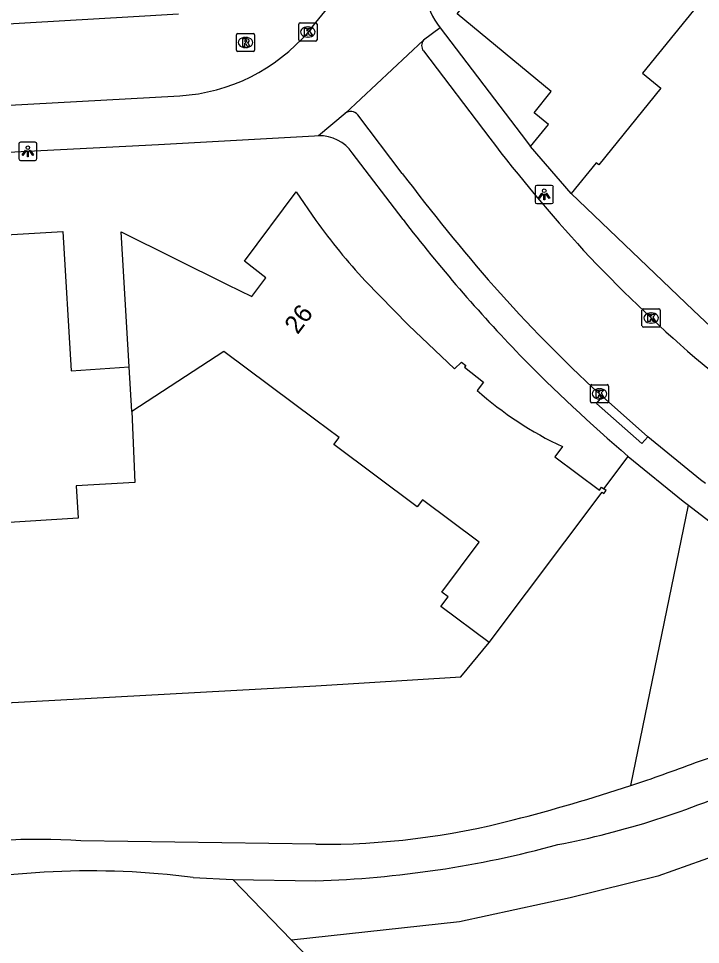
# Model space of a CAD drawing. Extents: x 159503 to 160347, y 382525 to 383272.
# Drawn here: x 159983.7 to 160021.1, y 382910.4 to 382961.2 of the extents above; entities that cross this region are included whole.
import ezdxf

# ---------------------------------------------------------------- set-up
doc = ezdxf.new("R2010")
doc.units = 0
for name, color, linetype in [('IMGEO_Fietspad_open', 7, 'Continuous'), ('IMGEO_Groenvoorziening', 7, 'Continuous'), ('IMGEO_Kolk', 7, 'Continuous'), ('IMGEO_Lichtpunt', 7, 'Continuous'), ('IMGEO_Muur', 7, 'Continuous'), ('IMGEO_Pand', 7, 'Continuous'), ('IMGEO_Pand_nummerreeks', 7, 'Continuous'), ('IMGEO_Rijbaan_lokaal_open', 7, 'Continuous'), ('IMGEO_Rioolput', 7, 'Continuous'), ('IMGEO_Voetpad_halfverhard', 7, 'Continuous'), ('IMGEO_Voetpad_open', 7, 'Continuous')]:
    doc.layers.add(name, color=color, linetype=linetype)

msp = doc.modelspace()

# ---------------------------------------------------------------- linework, layer by layer
at = {"layer": 'IMGEO_Fietspad_open'}
for points in [[(160005.905, 382959.423), (160009.545, 382954.631)], [(160004.746, 382952.7), (160002.3, 382955.907)], [(160020.788, 382942.6), (160024.456, 382939.589)], [(160015.738, 382940.446), (160015.569, 382940.601)], [(160015.738, 382940.446), (160018.22, 382938.246)], [(160021.378, 382935.67), (160021.106, 382935.882), (160018.22, 382938.246)]]:
    msp.add_lwpolyline(points, dxfattribs=at)
for centre, radius, start, end in [((160006.291, 382959.72), 0.487, 141.8673, 217.5579), ((160001.906, 382955.602), 0.498, 37.7654, 127.7017), ((160081.386, 383009.489), 90.391, 217.36539, 222.45416), ((160092.923, 383019.042), 110.347, 216.95678, 221.11214), ((160075.343, 383005.287), 83.102, 223.12889, 228.96758), ((160068.005, 382997.931), 77.694, 221.46522, 227.5527)]:
    msp.add_arc(centre, radius, start, end, dxfattribs=at)
at = {"layer": 'IMGEO_Groenvoorziening'}
for points in [[(160015.807, 382935.383), (160017.142, 382937.168)], [(160017.276, 382919.096), (160020.444, 382934.49)], [(159935.493, 382907.023), (159952.688, 382921.969), (160000, 382924.568), (160007.956, 382925.066), (160009.503, 382926.949)], [(160026.463, 382917.219), (160023.698, 382915.886), (160018.766, 382914.115), (160013.958, 382912.93), (160007.888, 382911.617), (159998.661, 382910.612)], [(159998.661, 382910.612), (159995.441, 382913.932)], [(159998.661, 382910.612), (159999.841, 382909.394), (160004.058, 382905.797), (160007.951, 382902.99), (160014.173, 382899.282), (160017.864, 382897.378), (160025.056, 382894.371), (160025.314, 382894.239)]]:
    msp.add_lwpolyline(points, dxfattribs=at)
at = {"layer": 'IMGEO_Kolk'}
for p, q in [((159999.066, 382960.039), (159999.066, 382960.891)), ((159999.141, 382960.965), (159999.993, 382960.965)), ((159999.554, 382960.745), (159999.579, 382960.745)), ((160000.067, 382960.891), (160000.067, 382960.039)), ((159999.577, 382960.185), (159999.552, 382960.185)), ((159999.993, 382959.965), (159999.141, 382959.965)), ((160017.896, 382944.34), (160017.896, 382945.192)), ((160017.971, 382945.266), (160018.823, 382945.266)), ((160018.384, 382945.046), (160018.409, 382945.046)), ((160018.897, 382945.192), (160018.897, 382944.34)), ((160018.823, 382944.266), (160017.971, 382944.266)), ((160018.407, 382944.486), (160018.382, 382944.486)), ((160015.065, 382940.177), (160015.065, 382941.029)), ((160015.14, 382941.103), (160015.992, 382941.103)), ((160015.553, 382940.883), (160015.578, 382940.883)), ((160016.066, 382941.029), (160016.066, 382940.177)), ((160015.576, 382940.323), (160015.551, 382940.323)), ((160015.992, 382940.103), (160015.14, 382940.103))]:
    msp.add_line(p, q, dxfattribs=at)
for points in [[(159999.066, 382960.039), (159999.066, 382960.891)], [(159999.141, 382960.965), (159999.993, 382960.965)], [(159999.387, 382960.665), (159999.51, 382960.665), (159999.51, 382960.514), (159999.64, 382960.665), (159999.804, 382960.665), (159999.658, 382960.514), (159999.811, 382960.265), (159999.659, 382960.265), (159999.574, 382960.429), (159999.51, 382960.362), (159999.51, 382960.265), (159999.387, 382960.265), (159999.387, 382960.665)], [(160000.067, 382960.891), (160000.067, 382960.039)], [(159999.993, 382959.965), (159999.141, 382959.965)], [(160017.896, 382944.34), (160017.896, 382945.192)], [(160017.971, 382945.266), (160018.823, 382945.266)], [(160018.217, 382944.966), (160018.34, 382944.966), (160018.34, 382944.815), (160018.47, 382944.966), (160018.634, 382944.966), (160018.488, 382944.815), (160018.641, 382944.566), (160018.489, 382944.566), (160018.404, 382944.73), (160018.34, 382944.663), (160018.34, 382944.566), (160018.217, 382944.566), (160018.217, 382944.966)], [(160018.897, 382945.192), (160018.897, 382944.34)], [(160018.823, 382944.266), (160017.971, 382944.266)], [(160015.065, 382940.177), (160015.065, 382941.029)], [(160015.14, 382941.103), (160015.992, 382941.103)], [(160015.386, 382940.803), (160015.509, 382940.803), (160015.509, 382940.652), (160015.639, 382940.803), (160015.803, 382940.803), (160015.657, 382940.652), (160015.81, 382940.403), (160015.658, 382940.403), (160015.573, 382940.567), (160015.509, 382940.5), (160015.509, 382940.403), (160015.386, 382940.403), (160015.386, 382940.803)], [(160016.066, 382941.029), (160016.066, 382940.177)], [(160015.992, 382940.103), (160015.14, 382940.103)]]:
    msp.add_lwpolyline(points, dxfattribs=at)
for centre, start, end in [((159999.143, 382960.889), 91.552, 178.448), ((159999.143, 382960.889), 91.552, 178.448), ((159999.991, 382960.889), 1.552, 88.448), ((159999.991, 382960.889), 1.552, 88.448), ((159999.143, 382960.041), 181.552, 268.448), ((159999.143, 382960.041), 181.552, 268.448), ((159999.991, 382960.041), 271.552, 358.448), ((159999.991, 382960.041), 271.552, 358.448), ((160017.973, 382945.19), 91.552, 178.448), ((160017.973, 382945.19), 91.552, 178.448), ((160018.821, 382945.19), 1.552, 88.448), ((160018.821, 382945.19), 1.552, 88.448), ((160017.973, 382944.342), 181.552, 268.448), ((160017.973, 382944.342), 181.552, 268.448), ((160018.821, 382944.342), 271.552, 358.448), ((160018.821, 382944.342), 271.552, 358.448), ((160015.142, 382941.027), 91.552, 178.448), ((160015.142, 382941.027), 91.552, 178.448), ((160015.99, 382941.027), 1.552, 88.448), ((160015.99, 382941.027), 1.552, 88.448), ((160015.142, 382940.179), 181.552, 268.448), ((160015.142, 382940.179), 181.552, 268.448), ((160015.99, 382940.179), 271.552, 358.448), ((160015.99, 382940.179), 271.552, 358.448)]:
    msp.add_arc(centre, 0.0765, start, end, dxfattribs=at)
for centre, major_axis, ratio, start_param, end_param in [((159999.553, 382960.465), (-0.387, 0.002), 0.722429, 4.712389, 7.853982), ((159999.578, 382960.465), (-0.39, 0.002), 0.717154, 1.570796, 4.712389), ((160018.383, 382944.766), (-0.387, 0.002), 0.722429, 4.712389, 7.853982), ((160018.408, 382944.766), (-0.39, 0.002), 0.717154, 1.570796, 4.712389), ((160015.552, 382940.603), (-0.387, 0.002), 0.722429, 4.712389, 7.853982), ((160015.577, 382940.603), (-0.39, 0.002), 0.717154, 1.570796, 4.712389)]:
    msp.add_ellipse(centre, major_axis=major_axis, ratio=ratio, start_param=start_param, end_param=end_param, dxfattribs=at)
at = {"layer": 'IMGEO_Lichtpunt'}
for p, q in [((159983.701, 382954.317), (159983.701, 382953.51)), ((159983.701, 382954.317), (159983.701, 382953.51)), ((159984.603, 382954.412), (159983.795, 382954.412)), ((159984.603, 382954.412), (159983.795, 382954.412)), ((159984.697, 382953.51), (159984.697, 382954.317)), ((159984.697, 382953.51), (159984.697, 382954.317)), ((159983.795, 382953.416), (159984.603, 382953.416)), ((159983.795, 382953.416), (159984.603, 382953.416)), ((160012.035, 382951.947), (160012.035, 382951.14)), ((160012.035, 382951.947), (160012.035, 382951.14)), ((160012.937, 382952.042), (160012.129, 382952.042)), ((160012.937, 382952.042), (160012.129, 382952.042)), ((160013.031, 382951.14), (160013.031, 382951.947)), ((160013.031, 382951.14), (160013.031, 382951.947)), ((160012.129, 382951.046), (160012.937, 382951.046)), ((160012.129, 382951.046), (160012.937, 382951.046))]:
    msp.add_line(p, q, dxfattribs=at)
for points in [[(159984.075, 382953.981), (159984.114, 382953.953), (159983.926, 382953.691), (159983.888, 382953.718), (159984.075, 382953.981)], [(159984.177, 382953.933), (159984.224, 382953.933), (159984.224, 382953.611), (159984.177, 382953.611), (159984.177, 382953.933)], [(159984.287, 382953.953), (159984.325, 382953.98), (159984.512, 382953.718), (159984.473, 382953.69), (159984.287, 382953.953)], [(160012.409, 382951.611), (160012.448, 382951.583), (160012.26, 382951.321), (160012.222, 382951.348), (160012.409, 382951.611)], [(160012.511, 382951.563), (160012.558, 382951.563), (160012.558, 382951.241), (160012.511, 382951.241), (160012.511, 382951.563)], [(160012.621, 382951.583), (160012.659, 382951.61), (160012.846, 382951.348), (160012.807, 382951.32), (160012.621, 382951.583)]]:
    msp.add_lwpolyline(points, dxfattribs=at)
for centre in [(159984.2, 382954.115), (160012.534, 382951.745)]:
    msp.add_circle(centre, 0.0994, dxfattribs=at)
for centre, start, end in [((159983.795, 382954.317), 90, 180), ((159983.795, 382954.317), 90, 180), ((159984.603, 382954.317), 0, 90), ((159984.603, 382954.317), 0, 90), ((159983.795, 382953.51), 180, 270), ((159983.795, 382953.51), 180, 270), ((159984.603, 382953.51), 270, 0), ((159984.603, 382953.51), 270, 360), ((160012.129, 382951.947), 90, 180), ((160012.129, 382951.947), 90, 180), ((160012.937, 382951.947), 0, 90), ((160012.937, 382951.947), 0, 90), ((160012.129, 382951.14), 180, 270), ((160012.129, 382951.14), 180, 270), ((160012.937, 382951.14), 270, 0), ((160012.937, 382951.14), 270, 360)]:
    msp.add_arc(centre, 0.0946, start, end, dxfattribs=at)
at = {"layer": 'IMGEO_Muur'}
msp.add_lwpolyline([(160014.004, 382951.592), (160020.709, 382945.19)], dxfattribs=at)
at = {"layer": 'IMGEO_Pand'}
for points in [[(160011.78, 382954.169), (160012.771, 382955.393), (160011.986, 382956.029), (160012.916, 382957.191), (160007.749, 382961.454), (160012.437, 382967.265), (160013.346, 382966.541), (160016.393, 382970.234), (160017.292, 382969.479), (160020.71, 382973.659), (160024.597, 382970.514), (160034.771, 382962.282), (160035.463, 382963.138), (160039.738, 382959.678), (160032.064, 382950.194), (160028.799, 382952.836), (160029.96, 382954.246), (160031.282, 382955.879), (160022.074, 382963.331), (160017.918, 382958.195), (160018.929, 382957.378), (160015.521, 382953.167), (160015.375, 382953.286), (160014.004, 382951.592)], [(160014.004, 382951.592), (160011.78, 382954.169)], [(159989.763, 382942.076), (159989.318, 382949.49), (159995.132, 382946.61), (159996.488, 382945.938), (159997.261, 382946.967), (159996.091, 382947.877), (159998.929, 382951.684), (160000, 382950.12)], [(159989.908, 382939.638), (159990.066, 382935.741), (159986.85, 382935.55), (159986.956, 382933.774), (159978.486, 382933.238), (159978.209, 382937.627), (159977.093, 382937.562), (159976.788, 382942.385), (159975.68, 382942.311), (159975.504, 382945.337), (159975.215, 382950.328), (159980.908, 382950.668), (159981.031, 382949.203), (159983.01, 382949.322), (159986.119, 382949.51), (159986.572, 382941.868), (159989.763, 382942.076)], [(160002.7, 382946.812), (160005.083, 382944.371), (160007.614, 382941.975), (160007.996, 382942.341), (160008.233, 382942.163), (160008.156, 382942.059), (160009.209, 382941.236), (160008.85, 382940.79)], [(160009.503, 382926.949), (160006.867, 382928.928), (160007.264, 382929.458), (160006.918, 382929.718), (160008.967, 382932.449), (160005.846, 382934.79), (160005.569, 382934.389), (160000.995, 382937.827), (160001.276, 382938.205), (160000, 382939.157), (159994.951, 382942.922), (159989.908, 382939.638)], [(159989.908, 382939.638), (159989.763, 382942.076)], [(160013.538, 382937.7), (160013.118, 382937.14), (160015.556, 382935.309), (160015.682, 382935.477), (160015.807, 382935.383)], [(160009.503, 382926.949), (160015.706, 382935.209), (160015.81, 382935.13), (160015.93, 382935.29), (160015.807, 382935.383)]]:
    msp.add_lwpolyline(points, dxfattribs=at)
for centre, radius, start, end in [((160029.875, 382971.748), 36.882, 215.9029, 222.54), ((160021.675, 382955.147), 19.251, 228.2247, 244.9952)]:
    msp.add_arc(centre, radius, start, end, dxfattribs=at)
at = {"layer": 'IMGEO_Rijbaan_lokaal_open'}
for points in [[(159999.59, 382960.475), (160000, 382960.98), (160004.421, 382966.424)], [(159992.466, 382961.44), (159989.696, 382961.282), (159982.453, 382960.859)], [(160006.829, 382960.689), (160005.908, 382960.021)], [(160001.602, 382955.996), (160005.908, 382960.021)], [(159982.87, 382956.422), (159992.548, 382956.964)], [(160001.602, 382955.996), (160000.149, 382954.763)], [(160000.149, 382954.763), (159999.933, 382954.745), (159991.369, 382954.262), (159973.432, 382953.353)]]:
    msp.add_lwpolyline(points, dxfattribs=at)
for centre, radius, start, end in [((160009.628, 382962.985), 3.62, 154.4733, 219.3669), ((159991.946, 382966.989), 10.043, 273.4358, 319.5641)]:
    msp.add_arc(centre, radius, start, end, dxfattribs=at)
at = {"layer": 'IMGEO_Rioolput'}
for p, q in [((159995.643, 382959.463), (159995.643, 382960.315)), ((159995.718, 382960.389), (159996.57, 382960.389)), ((159996.131, 382960.169), (159996.156, 382960.169)), ((159996.644, 382960.315), (159996.644, 382959.463)), ((159996.154, 382959.609), (159996.129, 382959.609)), ((159996.57, 382959.389), (159995.718, 382959.389))]:
    msp.add_line(p, q, dxfattribs=at)
for points in [[(159995.643, 382959.463), (159995.643, 382960.315)], [(159995.718, 382960.389), (159996.57, 382960.389)], [(159996.232, 382960.087), (159995.98, 382960.089), (159995.98, 382959.689)], [(159996.644, 382960.315), (159996.644, 382959.463)], [(159995.98, 382959.689), (159996.104, 382959.689), (159996.104, 382959.851), (159996.115, 382959.851)], [(159996.158, 382960.008), (159996.104, 382960.008), (159996.104, 382959.927)], [(159996.104, 382959.927), (159996.156, 382959.927)], [(159996.162, 382959.822), (159996.233, 382959.689), (159996.373, 382959.689), (159996.308, 382959.815)], [(159996.57, 382959.389), (159995.718, 382959.389)]]:
    msp.add_lwpolyline(points, dxfattribs=at)
for centre, radius, start, end in [((159995.72, 382960.313), 0.0765, 91.552, 178.448), ((159995.72, 382960.313), 0.0765, 91.552, 178.448), ((159996.231, 382959.977), 0.109, 350.3612, 89.416), ((159996.568, 382960.313), 0.0765, 1.552, 88.448), ((159996.568, 382960.313), 0.0765, 1.552, 88.448), ((159996.114, 382959.798), 0.0533, 26.0293, 88.6989), ((159996.14, 382960.116), 0.19, 274.7715, 282.9687), ((159996.164, 382959.912), 0.0964, 77.0061, 93.1865), ((159996.178, 382959.969), 0.0378, 276.6634, 79.6772), ((159996.229, 382959.977), 0.112, 277.5842, 350.9817), ((159996.213, 382959.762), 0.108, 29.5134, 73.7905), ((159995.72, 382959.465), 0.0765, 181.552, 268.448), ((159995.72, 382959.465), 0.0765, 181.552, 268.448), ((159996.568, 382959.465), 0.0765, 271.552, 358.448), ((159996.568, 382959.465), 0.0765, 271.552, 358.448)]:
    msp.add_arc(centre, radius, start, end, dxfattribs=at)
for centre, major_axis, ratio, start_param, end_param in [((159996.13, 382959.889), (-0.387, 0.002), 0.722429, 4.712389, 7.853982), ((159996.155, 382959.889), (-0.39, 0.002), 0.717154, 1.570796, 4.712389)]:
    msp.add_ellipse(centre, major_axis=major_axis, ratio=ratio, start_param=start_param, end_param=end_param, dxfattribs=at)
at = {"layer": 'IMGEO_Voetpad_halfverhard'}
for points in [[(160000, 382915.872), (159987.109, 382916.059)], [(159993.278, 382914.055), (159995.441, 382913.932)], [(159995.441, 382913.932), (160000, 382913.869)]]:
    msp.add_lwpolyline(points, dxfattribs=at)
for centre, radius, start, end in [((160012.526, 382945.745), 26.713, 288.1107, 307.8413), ((159986.98, 383010.262), 96.068, 288.3822, 290.63105), ((159987.431, 383009.179), 94.898, 284.27796, 288.33056), ((160004.319, 382962.136), 47.142, 280.9515, 294.4793), ((160000.326, 382957.707), 41.837, 269.5529, 284.5474), ((159984.823, 382885.202), 30.941, 85.7632, 102.0304), ((159998.241, 382971.072), 57.23, 271.7616, 285.2303), ((159987.63, 382869.501), 44.911, 82.7755, 102.4408)]:
    msp.add_arc(centre, radius, start, end, dxfattribs=at)
at = {"layer": 'IMGEO_Voetpad_open'}
for points in [[(160006.829, 382960.689), (160011.264, 382954.849), (160011.78, 382954.169)], [(160004.784, 382950.166), (160002.003, 382953.831)], [(160014.004, 382951.592), (160020.709, 382945.19), (160025.568, 382940.607)], [(160018.22, 382938.246), (160017.889, 382937.872), (160015.407, 382940.072), (160015.738, 382940.446)], [(160017.142, 382937.168), (160020.156, 382934.712), (160020.444, 382934.49)], [(160020.444, 382934.49), (160030.14, 382927.014)]]:
    msp.add_lwpolyline(points, dxfattribs=at)
for centre, radius, start, end in [((160000.212, 382952.579), 2.185, 34.9601, 91.6628), ((160074.156, 383003.511), 87.511, 217.55944, 223.99367), ((160074.022, 383003.922), 87.701, 224.24761, 229.56638)]:
    msp.add_arc(centre, radius, start, end, dxfattribs=at)

# ---------------------------------------------------------------- texts
at = {"layer": 'IMGEO_Pand_nummerreeks'}
msp.add_text('26', height=1, rotation=53.0856, dxfattribs=at).set_placement((159999.001, 382943.822))

doc.saveas('drawing.dxf')
